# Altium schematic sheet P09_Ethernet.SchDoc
size A2
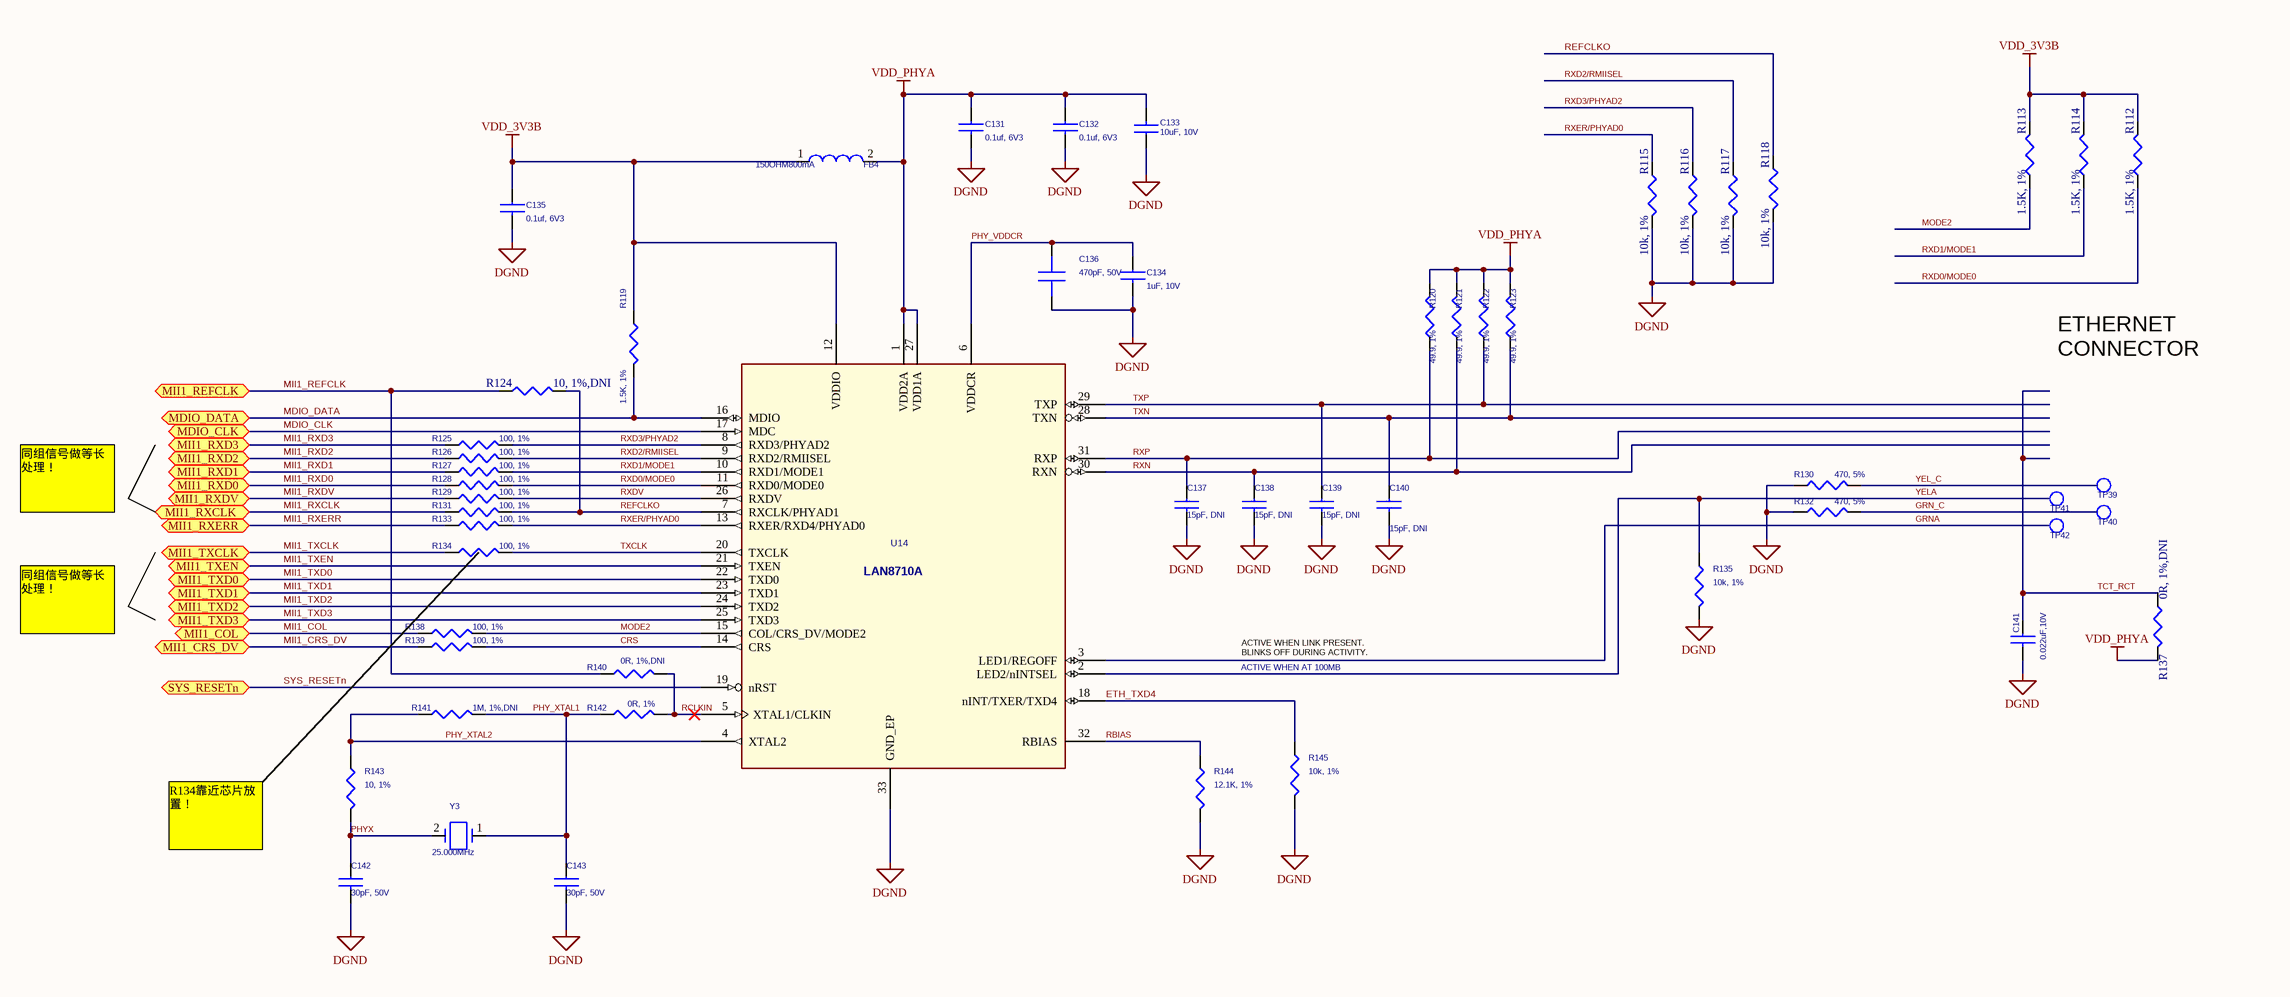
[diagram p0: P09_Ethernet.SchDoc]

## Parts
C131  0.1uf, 6V3  [402]
C132  0.1uf, 6V3  [402]
C133  10uF, 10V  [805]
C134  1uF, 10V  [402]
C135  0.1uf, 6V3  [402]
C136  470pF, 50V  [402]
C137  15pF, DNI  [402]
C138  15pF, DNI  [402]
C139  15pF, DNI  [402]
C140  15pF, DNI  [402]
C141  0.022uF,10V  [402]
C142  30pF, 50V  [402]
C143  30pF, 50V  [402]
FB4  150OHM800mA  [SM-7351-IND-0805]
R112  1.5K, 1%  [R0402]
R113  1.5K, 1%  [R0402]
R114  1.5K, 1%  [R0402]
R115  10k, 1%  [R0402]
R116  10k, 1%  [R0402]
R117  10k, 1%  [R0402]
R118  10k, 1%  [R0402]
R119  1.5K, 1%  [R0402]
R120  49.9, 1%  [R0402]
R121  49.9, 1%  [R0402]
R122  49.9, 1%  [R0402]
R123  49.9, 1%  [R0402]
R124  10, 1%,DNI  [R0402]
R125  100, 1%  [R0402]
R126  100, 1%  [R0402]
R127  100, 1%  [R0402]
R128  100, 1%  [R0402]
R129  100, 1%  [R0402]
R130  470, 5%  [R0402]
R131  100, 1%  [R0402]
R132  470, 5%  [R0402]
R133  100, 1%  [R0402]
R134  100, 1%  [R0402]
R135  10k, 1%  [R0402]
R137  0R, 1%,DNI  [R0402]
R138  100, 1%  [R0402]
R139  100, 1%  [R0402]
R140  0R, 1%,DNI  [R0402]
R141  1M, 1%,DNI  [R0402]
R142  0R, 1%  [R0402]
R143  10, 1%  [R0402]
R144  12.1K, 1%  [R0402]
R145  10k, 1%  [R0402]
TP39  TESTPT1  [tp1-8040]  (value not drawn)  (no BOM)
TP40  TESTPT1  [tp1-8040]  (value not drawn)  (no BOM)
TP41  TESTPT1  [tp1-8040]  (value not drawn)  (no BOM)
TP42  TESTPT1  [tp1-8040]  (value not drawn)  (no BOM)
U14  LAN8710A  [QFN32_5X5MM_EP3P3MM/LAN8710Ai-EZK/QFN-32]
Y3  25.000MHz  [XTAL150SMD_125X196]

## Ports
MDIO_CLK, MDIO_DATA, MII1_COL, MII1_CRS_DV, MII1_REFCLK, MII1_RXCLK, MII1_RXD0, MII1_RXD1, MII1_RXD2, MII1_RXD3, MII1_RXDV, MII1_RXERR, MII1_TXCLK, MII1_TXD0, MII1_TXD1, MII1_TXD2, MII1_TXD3, MII1_TXEN, SYS_RESETn

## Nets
DGND: C131.2 C132.2 C133.1 C134.2 C135.2 C136.2 C137.2 C138.2 C139.2 C140.2 C141.2 C142.2 C143.2 R115.2 R116.2 R117.2 R118.2 R130.1 R132.1 R135.2 R144.2 R145.2 U14.33(GND_EP)
VDD_3V3B: C135.1 FB4.1 R112.2 R113.2 R114.2 R119.1 U14.12(VDDIO)
VDD_PHYA: C131.1 C132.1 C133.2 FB4.2 R120.2 R121.2 R122.2 R123.2 R137.2 U14.1(VDD2A) U14.27(VDD1A)
CRS: R139.2 U14.14(CRS)
ETH_TXD4: R145.1 U14.18(nINT/TXER/TXD4)
GRN_C: R132.2 TP40.1(TP)
GRNA: TP42.1(TP) U14.3(LED1/REGOFF)
MDIO_CLK: U14.17(MDC) ; port MDIO_CLK
MDIO_DATA: R119.2 U14.16(MDIO) ; port MDIO_DATA
MII1_COL: R138.1 ; port MII1_COL
MII1_CRS_DV: R139.1 ; port MII1_CRS_DV
MII1_REFCLK: R124.1 R140.1 ; port MII1_REFCLK
MII1_RXCLK: R131.1 ; port MII1_RXCLK
MII1_RXD0: R128.1 ; port MII1_RXD0
MII1_RXD1: R127.1 ; port MII1_RXD1
MII1_RXD2: R126.1 ; port MII1_RXD2
MII1_RXD3: R125.1 ; port MII1_RXD3
MII1_RXDV: R129.1 ; port MII1_RXDV
MII1_RXERR: R133.1 ; port MII1_RXERR
MII1_TXCLK: R134.1 ; port MII1_TXCLK
MII1_TXD0: U14.22(TXD0) ; port MII1_TXD0
MII1_TXD1: U14.23(TXD1) ; port MII1_TXD1
MII1_TXD2: U14.24(TXD2) ; port MII1_TXD2
MII1_TXD3: U14.25(TXD3) ; port MII1_TXD3
MII1_TXEN: U14.21(TXEN) ; port MII1_TXEN
MODE2: R113.1 R138.2 U14.15(COL/CRS_DV/MODE2)
PHY_VDDCR: C134.1 C136.1 U14.6(VDDCR)
PHY_XTAL1: C143.1 R141.2 R142.1 Y3.1
PHY_XTAL2: R141.1 R143.1 U14.4(XTAL2)
PHYX: C142.1 R143.2 Y3.2
RBIAS: R144.1 U14.32(RBIAS)
RCLKIN: R140.2 R142.2 U14.5(XTAL1/CLKIN)
REFCLKO: R118.1 R124.2 R131.2 U14.7(RXCLK/PHYAD1)
RXD0/MODE0: R112.1 R128.2 U14.11(RXD0/MODE0)
RXD1/MODE1: R114.1 R127.2 U14.10(RXD1/MODE1)
RXD2/RMIISEL: R117.1 R126.2 U14.9(RXD2/RMIISEL)
RXD3/PHYAD2: R116.1 R125.2 U14.8(RXD3/PHYAD2)
RXDV: R129.2 U14.26(RXDV)
RXER/PHYAD0: R115.1 R133.2 U14.13(RXER/RXD4/PHYAD0)
RXN: C138.1 R121.1 U14.30(RXN)
RXP: C137.1 R120.1 U14.31(RXP)
SYS_RESETn: U14.19(nRST) ; port SYS_RESETn
TCT_RCT: C141.1 R137.1
TXCLK: R134.2 U14.20(TXCLK)
TXN: C140.1 R123.1 U14.28(TXN)
TXP: C139.1 R122.1 U14.29(TXP)
YEL_C: R130.2 TP39.1(TP)
YELA: R135.1 TP41.1(TP) U14.2(LED2/nINTSEL)

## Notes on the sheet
- ETHERNET
  CONNECTOR
- 同组信号做等长处理！
- ACTIVE WHEN LINK PRESENT.
  BLINKS OFF DURING ACTIVITY.
- ACTIVE WHEN AT 100MB
- R134靠近芯片放置！

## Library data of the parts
C131 C132 C135 = CAP_0.1uF_X7R_16V_10% 0402: CAP CER 0.1UF 6.3V 10% X5R 0402; Manufacturer: TDK Corporation; Manufacturer Part Number: C1005X5R0J104K050BA; Capacitance: 0.1µF; Tolerance: ?0%
C133 = CAP_4.7uF_X5R_6.3V_10%_0603: CAP CER 10UF 10V Y5V 0805; Manufacturer: TDK Corporation; Manufacturer Part Number: C2012Y5V1A106Z; Capacitance: 10µF; Tolerance: -20%, +80%; Temperature Coefficient: Y5V (F)
C134 = CAP_1.0UF_X5R_10V_10%_0402: CAP CER 1UF 10V 10% X5R 0402; Manufacturer: AVX Corporation; Manufacturer Part Number: 0402ZD105KAT2A; Capacitance: 1.0µF; Tolerance: ?0%
C136 = 470pF/5%/50V/C0G/0603_0: CAP CER 470PF 50V 10% X7R 0402; Manufacturer: Murata Electronics North America; Manufacturer Part Number: GRM155R71H471KA01D; Tolerance: ?0%
C137-C140 = CAP_0402_100pF_COG_50V: CAP CER 15PF 50V 5% NP0 0402; Manufacturer: TDK Corporation; Manufacturer Part Number: C1005C0G1H150J050BA; Tolerance: ?%; Temperature Coefficient: C0G, NP0
C141 = CAP_0402_0.1uf_X5R_10V: CAP CER 0.022UF 10V 10% X7R 0402; Manufacturer: Taiyo Yuden; Manufacturer Part Number: LMK105B7223KV-F; Capacitance: 0.022µF; Tolerance: ?0%
C142 C143 = CAP_30PF_COG_50V_5%_0402: CAP CER 30PF 50V 5% NP0 0402; Manufacturer: TDK Corporation; Manufacturer Part Number: C1005C0G1H300J; Tolerance: ?%; Temperature Coefficient: C0G, NP0
FB4 = FER_180_200_0: FERRITE 800MA 150 OHM 0805 SMD; PartName: FerriteBead150ohm800mA; Mfr: Steward; MfrNum: LI0805H151R-10; TIIntPartnumber: 1L0010; Manufacturer: Laird-Signal Integrity Products; Vendor: Digikey; DC Resistance (DCR): 150 mOhm Max; Filter Type: Differential Mode - Single; Impedance @ Frequency: 150 Ohm @ 100MHz
R112-R114 = RES_10K_1/16W_1%_0402: RES 1.50K OHM 1/16W 1% 0402 SMD; Manufacturer: Yageo; Manufacturer Part Number: RC0402FR-071K5L; Power (Watts): 0.063W, 1/16W; Temperature Coefficient: ?00ppm/°C; Tolerance: ?%
R115-R118 R135 R145 = RES_10K_1/16W_1%_0402: RES 10K OHM 1/16W 5% 0402 SMD; Manufacturer: Rohm Semiconductor; Manufacturer Part Number: MCR01MZPJ103; Power (Watts): 0.063W, 1/16W; Temperature Coefficient: ?00ppm/°C; Tolerance: ?%
R119 = RES_1.5K_1/16W_5%_0402: RES 1.50K OHM 1/16W 1% 0402 SMD; Manufacturer: Yageo; Manufacturer Part Number: RC0402FR-071K5L; Power (Watts): 0.063W, 1/16W; Temperature Coefficient: ?00ppm/°C; Tolerance: ?%
R120-R123 = RES_4.7K_0402: RES 49.9 OHM 1/16W 1% 0402 SMD; Manufacturer: Yageo; Manufacturer Part Number: RC0402FR-0749R9L; Power (Watts): 0.063W, 1/16W; Resistance (Ohms): 49.9; Temperature Coefficient: ?00ppm/°C; Tolerance: ?%
R124 = RES_10K_1/16W_1%_0402: Resistor 10Kohm 1/16W 1% 0402; Manufacturer: Stackpole Electronics Inc; Manufacturer Part Number: RMCF0402FT10R0; Power (Watts): 0.063W, 1/16W; Resistance (Ohms): 10; Temperature Coefficient: ?00ppm/°C; Tolerance: ?%
R125 R126 R129 R134 R138 = 100-1/10W-1%-0603_4: RES 100 OHM 1/10W 5% 0402 SMD; PART#: Rohm MCR03EZPFX1000; Manufacturer: Panasonic Electronic Components; Manufacturer Part Number: ERJ-2RKF1000X; Resistance (Ohms): 100; Power (Watts): 0.1W, 1/10W; Temperature Coefficient: ?00ppm/°C
R127 R128 R131 R133 R139 = RES_100_1/10W_5%_0402: RES 100 OHM 1/10W 5% 0402 SMD; Manufacturer: Panasonic Electronic Components; Manufacturer Part Number: ERJ-2RKF1000X; Resistance (Ohms): 100; Power (Watts): 0.1W, 1/10W; Temperature Coefficient: ?00ppm/°C; Tolerance: ?%
R130 R132 = RES_470_1/10W_5%_0402: RES 470 OHM 1/10W 5% 0402 SMD; Manufacturer: Panasonic Electronic Components; Manufacturer Part Number: ERJ-2GEJ471X; Resistance (Ohms): 470; Power (Watts): 0.1W, 1/10W; Temperature Coefficient: ?00ppm/°C; Tolerance: ?%
R137 R140 R142 = RES_0_1/16W_1%_0402: RES 0.0 OHM 1/16W 0402 SMD; Manufacturer: Yageo; Manufacturer Part Number: RC0402JR-070RL; Power (Watts): 0.063W, 1/16W; Resistance (Ohms): 0.0; Tolerance: Jumper
R141 = RES_1M_1/16W_1%_0402: RES 1M OHM 1/16W 1% 0402 SMD; Manufacturer: Stackpole Electronics Inc; Manufacturer Part Number: RMCF0402FT1M00; Power (Watts): 0.063W, 1/16W; Temperature Coefficient: ?00ppm/°C; Tolerance: ?%
R143 = RES_10K_1/16W_1%_0402: RES 10 OHM 1/16W 1% 0402 SMD; Manufacturer: Stackpole Electronics Inc; Manufacturer Part Number: RMCF0402FT10R0; Resistance (Ohms): 10; Power (Watts): 0.063W, 1/16W; Temperature Coefficient: ?00ppm/°C; Tolerance: ?%
R144 = RES_12.1K_1/16W_1%_0402: RES 12.1K OHM 1/16W 1% 0402 SMD; Manufacturer: Yageo; Manufacturer Part Number: RC0402FR-0712K1L; Power (Watts): 0.063W, 1/16W; Temperature Coefficient: ?00ppm/°C; Tolerance: ?%
U14 = LAN8710 QFN32_1: Ethernet ICs 10/100 Ethernet XCVR w/HPAutoMDIX FlexPwr; PART#: SMSC LAN8710A-EZK; Manufacturer: Microchip Technology; Manufacturer Part Number: LAN8710A-EZK-TR; Data Rate: 125 Mb/s; Number of Transceivers: 1; Standard Supported: 802.3, 802.3u; Supply Voltage - Max: 3.6 V; Supply Voltage - Min: 1.6 V, 3 V
Y3 = Suntsu ITEMP 25MHz _0.005% 20pf: Manufacturer: Abracon Corporation; Manufacturer Part Number: ABM3-25.000MHZ-B2-T; Frequency: 25MHz; Frequency Stability: ?0ppm; Load Capacitance: 18pF; ESR (Equivalent Series Resistance): 50 Ohm; Operating Mode: Fundamental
